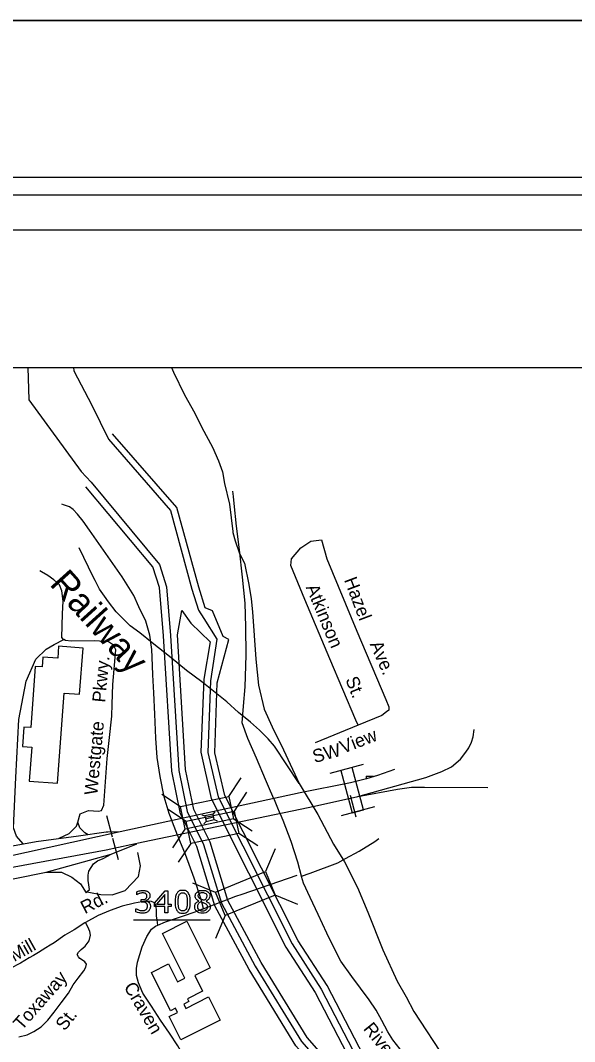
# Model space of a CAD drawing. Extents: x 925297 to 940193, y 663541 to 689899.
# Drawn here: x 929507 to 930141, y 688730 to 689899 of the extents above; entities that cross this region are included whole.
import ezdxf

# ---------------------------------------------------------------- set-up
doc = ezdxf.new("R2010")
doc.units = 0
for name, color, linetype in [('Default', 7, 'Continuous'), ('Sheet Cutting Line CELL', 7, 'Continuous'), ('Sheet Plot Border Inside CELL', 7, 'Continuous'), ('Sheet Plot Border Outside CELL', 7, 'Continuous'), ('Sheet Title CELL', 7, 'Continuous')]:
    doc.layers.add(name, color=color, linetype=linetype)

msp = doc.modelspace()

# ---------------------------------------------------------------- linework, layer by layer
at = {"layer": 'Default'}
for p, q in [((929670.8, 689194.5), (929666.1, 689249.7)), ((929893.7, 689092.1), (929844.3, 689071.9)), ((929899.4, 689047.3), (929861.1, 689037)), ((929902.7, 689034), (929911.1, 689034)), ((929902.7, 689034), (929902.7, 689030.8)), ((929745.5, 689010.5), (929759.6, 689032)), ((929668.8, 689013.3), (929690.3, 688999.2)), ((929765.9, 689015.4), (929751.8, 688993.9)), ((929884.6, 689012), (929890.9, 688987.5)), ((929912.4, 688998.8), (929874.1, 688988.5)), ((929605.5, 688989), (929612.1, 688964.6)), ((929696.7, 688982.1), (929675.2, 688996.2)), ((929714.8, 688989.8), (929718.3, 688988.3)), ((929719, 688985.2), (929728.2, 688987.3)), ((929727.6, 688990.4), (929730.1, 688993.2)), ((929717.1, 688979.3), (929719.6, 688982.1)), ((929728.9, 688984.3), (929732.4, 688982.8)), ((929750.7, 688985.3), (929772.2, 688971.2)), ((929681.5, 688951.9), (929695.7, 688973.4)), ((929778.6, 688954), (929757.1, 688968.2)), ((929612.4, 688962.9), (929618.9, 688938.4)), ((929701.9, 688956.9), (929687.7, 688935.4)), ((929536.6, 688924), (929610.8, 688944.5)), ((929798.5, 688950.7), (929787.6, 688924.6)), ((929730.5, 688900.6), (929704.4, 688911.5)), ((929824.7, 688886.9), (929798.6, 688897.8)), ((929636.5, 688869.6), (929724.3, 688869.6)), ((929741.2, 688874.4), (929730.3, 688848.3))]:
    msp.add_line(p, q, dxfattribs=at)
for points in [[(929515.7, 689501.3), (929516.7, 689464.3), (929576.5, 689382.4), (929587.9, 689370.1), (929666.2, 689275.9), (929674.1, 689250.4), (929678.7, 689194.9), (929688.2, 689040.4), (929697.8, 688993.3), (929716.5, 688955.8), (929737.2, 688888.6), (929775.8, 688816.5), (929828.8, 688730.2), (929922.8, 688623.5), (929941.6, 688576.4), (929958.6, 688487.1), (929956.3, 688377.5), (929939.7, 688289.2), (929888.3, 688106.6), (929879.7, 688005.5), (929891.9, 687940.2), (929922, 687869), (929962.6, 687811.5)], [(929567.7, 689501.3), (929568.3, 689497.5), (929588.8, 689458.5), (929607.8, 689419.6), (929678.7, 689337.7), (929703.4, 689248), (929711, 689223.9), (929717, 689214.4), (929731.8, 689190.6), (929724.5, 689142.8), (929721.4, 689061), (929733.2, 689010.1), (929817.9, 688841.9), (929851.3, 688790.3), (929897.9, 688700.4)], [(929680, 689501.3), (929682.3, 689496.3), (929694.7, 689470.3), (929706.8, 689449.3), (929714.6, 689432.8), (929726.7, 689410.4), (929733.9, 689394.7), (929738.2, 689382.1), (929740.8, 689368.7), (929746.5, 689345.2), (929750.3, 689313.8), (929750.3, 689312.7), (929752.7, 689303), (929757.7, 689288.7), (929763.7, 689277.5), (929768.4, 689253.3), (929771.2, 689236.8), (929772.7, 689221.8), (929776.3, 689167.9), (929779.4, 689137.9), (929785.9, 689110.4), (929795.1, 689090.5), (929808.3, 689063.9), (929826, 689025.3)], [(929711.1, 689250.1), (929686, 689341.2), (929612.6, 689425.5)], [(929666.1, 689249.7), (929658.6, 689273.5), (929581.8, 689364.9)], [(929800.9, 688999.1), (929797.7, 689006.6), (929797.5, 689007), (929793.3, 689016.8), (929787.4, 689030.2), (929777.1, 689054.6), (929767.2, 689076.8), (929761, 689094.9), (929762.5, 689114.1), (929764.1, 689136.1), (929765.4, 689172.2), (929765.2, 689204.9), (929764.1, 689231.8), (929761.3, 689261.6), (929757.7, 689292.8), (929754.4, 689320.1), (929751.6, 689345.8), (929751, 689353.9), (929750.1, 689359.9)], [(929716.7, 688882.3), (929713.9, 688892.8), (929705.8, 688917), (929695.9, 688944.4), (929689.5, 688959.7), (929687.4, 688965), (929686.9, 688966.2), (929681.2, 688981.2), (929680.8, 688982.2), (929677.3, 688991.1), (929671.7, 689010.4), (929666.8, 689033.3), (929663.6, 689055.2), (929662.2, 689077.5), (929660.9, 689104.7), (929659.7, 689129.4), (929658.7, 689149.7), (929657.8, 689170.2), (929657.3, 689178.7), (929655.2, 689195.3), (929650.4, 689211.3), (929642.6, 689227.5), (929636.8, 689240.7), (929623.6, 689261.8), (929586.2, 689315.5), (929578.8, 689325.5), (929572.3, 689333.5), (929567.3, 689339), (929563.1, 689342.1), (929556.2, 689344.5), (929554.3, 689345.2)], [(929893.7, 689092.1), (929891.1, 689098), (929861.3, 689168.1), (929832.7, 689235.9), (929816.7, 689275), (929817.4, 689282.7), (929827.9, 689295), (929839.4, 689302.7), (929851.5, 689304.4)], [(929851.5, 689304.4), (929857.7, 689282.4), (929891.9, 689199.6), (929925.1, 689121.6), (929928.6, 689113.3), (929928.9, 689109.5), (929926.2, 689107.3)], [(929826, 689025.3), (929797.9, 689068.1), (929790.5, 689076.7), (929780.6, 689086.6), (929770.5, 689095.7), (929756.5, 689106.8), (929743.3, 689118.8), (929714.5, 689141.7), (929697.3, 689154.7), (929679.5, 689169.2), (929657.7, 689186.5), (929643.7, 689197.8), (929632.7, 689205.9), (929616.6, 689221.9), (929607.7, 689233.4), (929603.1, 689240), (929597.7, 689247.8), (929592.5, 689257.9), (929586.9, 689269), (929585.1, 689273.2), (929574.3, 689295)], [(929556.9, 689190.1), (929555.9, 689190.6), (929554.4, 689192.4), (929554.3, 689192.7), (929555.3, 689219.8), (929555.8, 689234.1), (929554.5, 689245.9), (929551.7, 689252.9), (929545.4, 689258.7), (929538.3, 689263.5), (929531, 689267.6), (929529.3, 689268.7)], [(929739.1, 689193.8), (929726.8, 689222.9), (929718.6, 689226.3), (929711.1, 689250.1)], [(930095.1, 687665.9), (930073.2, 687695.8), (929968.9, 687816.4), (929929.1, 687872.9), (929899.6, 687942.6), (929887.7, 688005.9), (929896.1, 688105.1), (929947.4, 688287), (929964.2, 688376.1), (929966.6, 688486.9), (929949.5, 688577.9), (929930.2, 688626.5), (929835.3, 688735), (929782.7, 688820.5), (929744.6, 688891.7), (929724.1, 688958.2), (929705.4, 688995.9), (929696.1, 689041.5), (929686.7, 689195.4), (929691.8, 689223.6)], [(929691.8, 689223.6), (929702.1, 689209), (929724.4, 689187.5), (929716.8, 689144.9), (929713.4, 689061.3), (929725.4, 689008.2), (929810.8, 688838.3), (929844.4, 688786.2), (929890.8, 688696.7), (929953.1, 688629.1), (929964.3, 688608.9), (929973.2, 688567.4), (929978.8, 688538.1), (929993.3, 688402.8), (929987.5, 688330.5), (929952, 688204), (929933, 688166.4), (929911.3, 688098.1), (929902.9, 688020.3), (929916.9, 687936.8), (929949.5, 687869.5), (929990.4, 687823.1), (930042.1, 687777.3), (930109.6, 687684.7)], [(929499.2, 688974.9), (929501.9, 689032.2), (929505.3, 689098.7), (929513.6, 689142.4), (929524.7, 689167.8), (929536.6, 689179.2), (929545.8, 689184.5), (929556.9, 689190.1)], [(929572.7, 688981.2), (929575.6, 688990.9), (929584.8, 688994.5), (929596.4, 688993.8), (929599.8, 688994.7), (929602.6, 689000.8), (929606.4, 689053.9), (929608.5, 689074.5), (929611.7, 689102.4), (929611.7, 689102.5), (929612.2, 689116.2), (929612.9, 689138.8), (929616.4, 689178.3), (929613.7, 689183.6), (929608, 689187.4), (929592.2, 689188.9), (929565.1, 689188.3), (929558.8, 689189.2), (929556.9, 689190.1)], [(930085, 687652.8), (930060.4, 687686.3), (929956.3, 687806.5), (929915, 687865.1), (929884.2, 687937.9), (929871.6, 688005.1), (929880.3, 688108), (929932, 688291.4), (929948.4, 688379), (929950.6, 688487.3), (929933.8, 688574.9), (929915.4, 688620.5), (929822.4, 688725.4), (929768.8, 688812.5), (929729.7, 688885.5), (929708.8, 688953.5), (929690.1, 688990.6), (929680.2, 689039.4), (929670.8, 689194.5)], [(930119.8, 687697.9), (930054, 687788.2), (930002.3, 687833.8), (929963.8, 687876.6), (929932.7, 687939.6), (929918.8, 688018.6), (929926.5, 688093.3), (929947.2, 688159.2), (929967, 688198.1), (930003.3, 688327.4), (930012.8, 688406), (929994.3, 688542.8), (929988.5, 688569.2), (929980.2, 688613.3), (929966.1, 688638.6), (929905, 688704.1), (929858.3, 688794.3), (929825.1, 688845.5), (929741, 689011.9), (929729.4, 689060.7), (929732.2, 689140.7), (929745.7, 689190.3), (929739.1, 689193.8)], [(929926.2, 689107.3), (929920.8, 689103.1), (929893.7, 689092.1)], [(929893.1, 689010.7), (929970.9, 689032.4), (929989.3, 689039.3), (930000.3, 689044.7), (930010.7, 689053.3), (930016.7, 689061.5), (930020.4, 689066.4), (930023.4, 689072.7), (930025.3, 689078.9), (930026.2, 689087.1)], [(929935.3, 689041.5), (929928.7, 689039.2), (929915.8, 689034.8), (929903, 689030.7), (929884.8, 689026.4), (929827.3, 689014.8)], [(929826, 689025.3), (929847.4, 688990), (929865.4, 688956), (929877.8, 688936), (929892.7, 688906.4)], [(929827.3, 689014.8), (929621.3, 688970.3)], [(929836.4, 688998), (929846.9, 689000.2), (929893.1, 689010.7)], [(929893.1, 689010.7), (929938.6, 689018.9), (929954.7, 689021.2), (929969.5, 689021.2), (930041.9, 689021)], [(929828.7, 688919.5), (929824.5, 688935.3), (929817.1, 688959), (929807.7, 688983.2), (929804.6, 688990.5), (929804.4, 688990.9), (929800.9, 688999.1)], [(929647.6, 688958.6), (929836.4, 688998)], [(929510.2, 688956.5), (929502.4, 688965.2), (929499.2, 688974.9)], [(929551.4, 688962.9), (929562.8, 688968.3), (929571.2, 688976.8), (929572.7, 688981.2)], [(929584.7, 688966.8), (929580.8, 688968.9), (929575, 688974.9), (929572.7, 688981.2)], [(929606.9, 688969.7), (929605, 688969.6), (929573.5, 688965.3), (929525.1, 688958.8), (929451.3, 688945.4), (929434.4, 688942.9), (929419.9, 688943.1), (929409.1, 688943.8), (929393, 688947.6), (929370.7, 688956.8), (929354.8, 688964.4), (929342.4, 688968.8), (929332.5, 688970.5), (929324.5, 688970.7), (929316.1, 688969.5), (929303.7, 688965.6)], [(929621.3, 688970.3), (929458.3, 688934.5)], [(929621.3, 688970.3), (929606.9, 688969.7)], [(929400.2, 688911.9), (929605.3, 688949.6), (929647.6, 688958.6)], [(929610.8, 688944.5), (929640.4, 688956.3)], [(929828.7, 688919.5), (929838.8, 688922.8), (929870.5, 688934.7), (929879.1, 688939.5), (929894.9, 688948), (929912.6, 688959), (929917.4, 688962.5)], [(929536.6, 688924), (929553.9, 688923.9), (929565.9, 688918.3), (929575.8, 688910.5), (929582.3, 688900.5), (929583.1, 688901.4), (929587.4, 688900.6), (929599, 688898.6), (929612, 688897.9), (929626.8, 688903.1), (929642.2, 688918.9), (929644.4, 688931.3), (929641.6, 688946.6)], [(929583.1, 688901.4), (929586.1, 688904.3), (929585.4, 688909.4), (929584.4, 688914.6), (929584.4, 688920.5), (929585.4, 688925), (929588, 688929.5), (929590.6, 688933.5), (929595.3, 688936.8), (929601.6, 688939.8), (929610.8, 688944.5)], [(929402.4, 688899.9), (929411.1, 688901.7), (929470.2, 688910.8), (929534.5, 688923.5), (929536.6, 688924)], [(929823.5, 688920.1), (929760.3, 688898.5)], [(929941.7, 688721.3), (929933.2, 688732.3), (929927.6, 688741.2), (929920.7, 688754.4), (929914.4, 688766.2), (929906.2, 688778.1), (929896.1, 688791.4), (929886.5, 688804.5), (929873.8, 688822), (929866.8, 688835.4), (929857.8, 688854.4), (929847.9, 688875.5), (929838.6, 688895.1), (929830.9, 688911.3), (929828.8, 688919.1), (929828.7, 688919.5)], [(929892.7, 688906.4), (929904.8, 688878.4), (929921.8, 688835.2), (929938.3, 688799.1), (929948.6, 688781.4), (929957.3, 688764.4), (929994.4, 688708.1), (930021.2, 688670.3)], [(929640.2, 688898), (929640.1, 688898), (929640.1, 688901.5)], [(929679.4, 688884.6), (929675.7, 688884.6), (929675.7, 688877.6), (929672.5, 688877.6), (929672.5, 688884.6), (929660.5, 688884.6), (929660.5, 688888.5), (929672.6, 688902.6), (929675.7, 688902.6), (929675.7, 688887.3), (929679.4, 688887.3), (929679.4, 688884.6)], [(929672.5, 688887.3), (929672.5, 688898.6), (929662.8, 688887.3), (929672.5, 688887.3)], [(929760.3, 688898.5), (929753.1, 688896.1), (929714.1, 688881.1)], [(929664.4, 688863.5), (929663.5, 688869.3), (929662.8, 688873.7), (929662.6, 688879.3), (929662.3, 688885.4), (929660.5, 688889.1), (929656.9, 688890.6), (929650.1, 688890.7), (929637.8, 688888.5), (929623.5, 688885.1), (929609.8, 688880.3), (929595.9, 688874.5), (929581.7, 688866.4)], [(929639.3, 688878.6), (929639.3, 688882.1), (929639.6, 688882.1)], [(929646.6, 688889.8), (929645.1, 688889.8), (929645.1, 688892.6), (929646.3, 688892.6)], [(929650.4, 688891.5), (929650.4, 688891.3)], [(929664.4, 688863.5), (929673.2, 688867.2), (929692.7, 688873.8), (929706.9, 688878.6), (929716.7, 688882.3)], [(929711.2, 688890.9), (929711.2, 688891)], [(929719.5, 688890.9), (929719.5, 688890.8)], [(929581.7, 688866.4), (929580.9, 688866), (929568.4, 688858.1), (929558, 688851.9), (929545.5, 688843), (929541.2, 688840.6), (929536, 688837.6), (929527.9, 688832.1), (929521.9, 688828.6), (929517.2, 688825.8), (929507.2, 688819.7), (929495.2, 688813.7), (929486.4, 688808.8), (929475, 688803.2), (929470.6, 688794.8), (929469.9, 688791.4)], [(929505.4, 688735.5), (929514.6, 688737.7), (929522.5, 688741.6), (929530.9, 688747.1), (929538.6, 688754.5), (929545.6, 688763.7), (929553.7, 688774.4), (929561.9, 688785.7), (929567.5, 688795.2), (929573, 688802.8), (929579.7, 688811.1), (929582, 688815.3), (929582.5, 688818.9), (929580.9, 688821.3), (929577.1, 688824), (929575.2, 688825.3), (929573.4, 688827.3), (929572, 688829.8), (929573.5, 688832.4), (929576.7, 688835.4), (929581.1, 688839.2), (929585.6, 688845.3), (929587.2, 688851.8), (929586.5, 688856), (929585.5, 688858.6), (929584.7, 688860.8), (929581.7, 688866.4)], [(929700.3, 688701.3), (929699.6, 688702.5), (929695.2, 688711), (929687.3, 688725.2), (929677.5, 688739.9), (929667.3, 688754.8), (929657.1, 688770.5), (929647.3, 688785.6), (929642, 688797.5), (929640, 688805.9), (929640, 688813.7), (929641, 688821.2), (929646.5, 688838.4), (929651.7, 688850.4), (929657.1, 688858.7), (929661.8, 688862.3), (929664.4, 688863.5)]]:
    msp.add_lwpolyline(points, dxfattribs=at)
for points in [[(929549.6, 689025.7), (929557.2, 689128.8), (929574.8, 689127.5), (929578.7, 689180.4), (929550.8, 689182.5), (929549.8, 689168.7), (929532.7, 689170), (929531.9, 689158.9), (929524, 689159.4), (929518.8, 689089.4), (929511, 689090), (929509.4, 689067.9), (929520, 689067.1), (929517.1, 689028.1)], [(929873.9, 689040.5), (929886.9, 688991.9), (929899.6, 688995.3), (929886.6, 689043.9)], [(929690.3, 688999.2), (929745.5, 689010.6), (929750.8, 688984.9), (929695.7, 688973.4)], [(929757.1, 688968.2), (929701.9, 688956.8), (929696.6, 688982.5), (929751.8, 688993.9)], [(929719.6, 688982.1), (929728.9, 688984.2), (929727.6, 688990.4), (929718.3, 688988.3)], [(929798.6, 688897.8), (929741.3, 688874.3), (929730.3, 688901.1), (929787.6, 688924.6)], [(929697.6, 688867.9), (929724.4, 688814.6), (929706.5, 688805.6), (929715.5, 688787.7), (929698.1, 688779), (929699.7, 688775.9), (929694, 688773), (929696.4, 688768.2), (929722.3, 688781.2), (929735.6, 688754.6), (929690.5, 688732), (929677.1, 688758.7), (929687, 688763.6), (929684.6, 688768.4), (929678.9, 688765.5), (929656.9, 688809.2), (929676.7, 688819.1), (929687, 688798.6), (929695.3, 688802.7), (929669.6, 688853.9)]]:
    msp.add_lwpolyline(points, close=True, dxfattribs=at)
for points in [[(929640.1, 688901.5), (929641.2, 688902.1), (929643.2, 688902.6), (929645.2, 688903.1), (929647.1, 688903.1), (929648.9, 688903.1), (929650.3, 688902.8), (929651.7, 688902.5), (929652.8, 688901.7), (929654.1, 688900.9), (929654.7, 688899.8), (929655.3, 688898.6), (929655.3, 688897.1), (929655.3, 688895), (929653.8, 688893.5), (929652.4, 688891.9), (929650.4, 688891.5)], [(929646.3, 688892.6), (929648.8, 688892.6), (929650.4, 688893.6), (929651.9, 688894.7), (929651.9, 688896.7), (929651.9, 688897.7), (929651.5, 688898.3), (929651.1, 688899), (929650.4, 688899.5), (929649.7, 688899.9), (929648.9, 688900.1), (929648.1, 688900.2), (929647, 688900.2), (929645.4, 688900.2), (929643.6, 688899.7), (929641.8, 688899.1), (929640.2, 688898)], [(929701.5, 688890.1), (929701.5, 688883.4), (929699.3, 688880.2), (929697.2, 688877.1), (929692.8, 688877.1), (929688.3, 688877.1), (929686.2, 688880.3), (929684.2, 688883.5), (929684.2, 688890.1), (929684.2, 688896.8), (929686.3, 688899.9), (929688.4, 688903.1), (929692.8, 688903.1), (929697.3, 688903.1), (929699.4, 688899.9), (929701.5, 688896.7), (929701.5, 688890.1)], [(929697, 688882.5), (929697.6, 688883.8), (929697.8, 688885.7), (929698, 688887.5), (929698, 688890.1), (929698, 688892.7), (929697.8, 688894.5), (929697.6, 688896.4), (929697, 688897.7), (929696.4, 688899), (929695.4, 688899.7), (929694.4, 688900.3), (929692.8, 688900.3), (929691.2, 688900.3), (929690.2, 688899.7), (929689.2, 688899), (929688.6, 688897.7), (929688, 688896.5), (929687.8, 688894.5), (929687.6, 688892.5), (929687.6, 688890.1), (929687.6, 688887.5), (929687.8, 688885.7), (929687.9, 688883.9), (929688.5, 688882.5), (929689.1, 688881.2), (929690.1, 688880.5), (929691.1, 688879.8), (929692.8, 688879.8), (929694.4, 688879.8), (929695.4, 688880.5), (929696.5, 688881.2), (929697, 688882.5)], [(929711.2, 688891), (929709.2, 688892.1), (929708.2, 688893.4), (929707.2, 688894.7), (929707.2, 688896.6), (929707.2, 688899.4), (929709.5, 688901.3), (929711.9, 688903.2), (929715.4, 688903.2), (929719.2, 688903.2), (929721.4, 688901.4), (929723.7, 688899.6), (929723.7, 688896.8), (929723.7, 688895.1), (929722.6, 688893.5), (929721.5, 688891.8), (929719.5, 688890.9)], [(929720.4, 688896.8), (929720.4, 688898.6), (929719, 688899.6), (929717.6, 688900.7), (929715.4, 688900.7), (929713.3, 688900.7), (929712, 688899.7), (929710.6, 688898.7), (929710.6, 688897), (929710.6, 688895.8), (929711.3, 688894.9), (929712, 688894), (929713.3, 688893.3), (929714, 688893), (929715.1, 688892.5), (929716.3, 688892), (929717.4, 688891.7), (929719.1, 688892.8), (929719.7, 688894), (929720.4, 688895.2), (929720.4, 688896.8)], [(929654, 688889.6), (929654.8, 688888.9), (929655.3, 688887.8), (929655.8, 688886.7), (929655.8, 688885), (929655.8, 688883.3), (929655.2, 688881.9), (929654.6, 688880.4), (929653.4, 688879.4), (929652.2, 688878.2), (929650.5, 688877.6), (929648.8, 688877.1), (929646.7, 688877.1), (929644.7, 688877.1), (929642.6, 688877.6), (929640.6, 688878.1), (929639.3, 688878.6)], [(929639.6, 688882.1), (929641, 688881.2), (929643, 688880.6), (929644.9, 688880), (929646.7, 688880), (929647.7, 688880), (929648.9, 688880.3), (929650.1, 688880.7), (929650.9, 688881.4), (929651.6, 688882.1), (929652, 688883), (929652.4, 688883.9), (929652.4, 688885.2), (929652.4, 688886.6), (929652, 688887.5), (929651.5, 688888.4), (929650.8, 688888.9), (929650, 688889.4), (929649, 688889.6), (929647.9, 688889.8), (929646.6, 688889.8)], [(929650.4, 688891.3), (929651.2, 688891.1), (929652.2, 688890.7), (929653.2, 688890.3), (929654, 688889.6)], [(929724.3, 688884.6), (929724.3, 688881.3), (929721.8, 688879.2), (929719.3, 688877), (929715.4, 688877), (929711.4, 688877), (929709, 688879.1), (929706.6, 688881.2), (929706.6, 688884.5), (929706.6, 688886.6), (929707.8, 688888.3), (929709, 688890), (929711.2, 688890.9)], [(929720.9, 688884.2), (929720.9, 688885.8), (929720.2, 688886.7), (929719.5, 688887.7), (929717.5, 688888.6), (929716.7, 688889), (929715.8, 688889.3), (929714.9, 688889.6), (929713.3, 688890.2), (929711.8, 688889.3), (929710.9, 688887.9), (929710, 688886.5), (929710, 688884.8), (929710, 688882.5), (929711.5, 688881), (929713.1, 688879.5), (929715.5, 688879.5), (929717.9, 688879.5), (929719.4, 688880.8), (929720.9, 688882), (929720.9, 688884.2)], [(929719.5, 688890.8), (929721.8, 688889.8), (929723.1, 688888.3), (929724.3, 688886.8), (929724.3, 688884.6)]]:
    msp.add_open_spline(points, degree=3, dxfattribs=at)
at = {"layer": 'Sheet Cutting Line CELL'}
msp.add_line((925296.7, 689898.6), (938768.7, 689898.6), dxfattribs=at)
at = {"layer": 'Sheet Plot Border Inside CELL'}
msp.add_lwpolyline([(925400.7, 681278.2), (938732.7, 681278.2), (938732.7, 689719), (925400.7, 689719)], close=True, dxfattribs=at)
at = {"layer": 'Sheet Plot Border Outside CELL'}
msp.add_lwpolyline([(938768.7, 689898.6), (925296.7, 689898.6), (925296.7, 681098.7), (938768.7, 681098.7)], close=True, dxfattribs=at)
at = {"layer": 'Sheet Title CELL'}
for points in [[(938552.8, 689698.6), (926712.6, 689698.7)], [(938512.7, 689658.6), (927152.8, 689658.6)]]:
    msp.add_lwpolyline(points, dxfattribs=at)
msp.add_lwpolyline([(927148.4, 689501.3), (930192.1, 689501.3), (930192.1, 687400.3), (927148.4, 687400.3)], close=True, dxfattribs=at)

# ---------------------------------------------------------------- texts
at = {"layer": 'Default'}
for s, height, rotation, p in [('Railway', 30, 312.0776, (929539.4, 689253.1)), ('Hazel', 15, 290.6373, (929877.3, 689258.5)), ('Atkinson', 15, 292.6082, (929833.5, 689250)), ('Ave.', 15, 293.6332, (929906.6, 689184.9)), ('Pkwy.', 15, 84.757, (929604.1, 689117.7)), ('St.', 15, 291.3861, (929878.8, 689144.6)), ('Westgate', 15, 84.757, (929595, 689011.7)), ('View', 15, 21.2273, (929876.2, 689059.4)), ('SW', 15, 15.3382, (929843.7, 689048.8)), ('Rd.', 15, 27.0534, (929580.8, 688875.8)), ('Mill', 15, 29.2883, (929499.9, 688821.1)), ('Toxaway', 15, 48.7024, (929508.7, 688742.3)), ('Craven', 15, 300.5875, (929624.9, 688792.8)), ('St.', 15, 51.7815, (929557.7, 688741.5)), ('Riverside', 15, 308.7695, (929898.8, 688744.6))]:
    msp.add_text(s, height=height, rotation=rotation, dxfattribs=at).set_placement(p)

doc.saveas('drawing.dxf')
